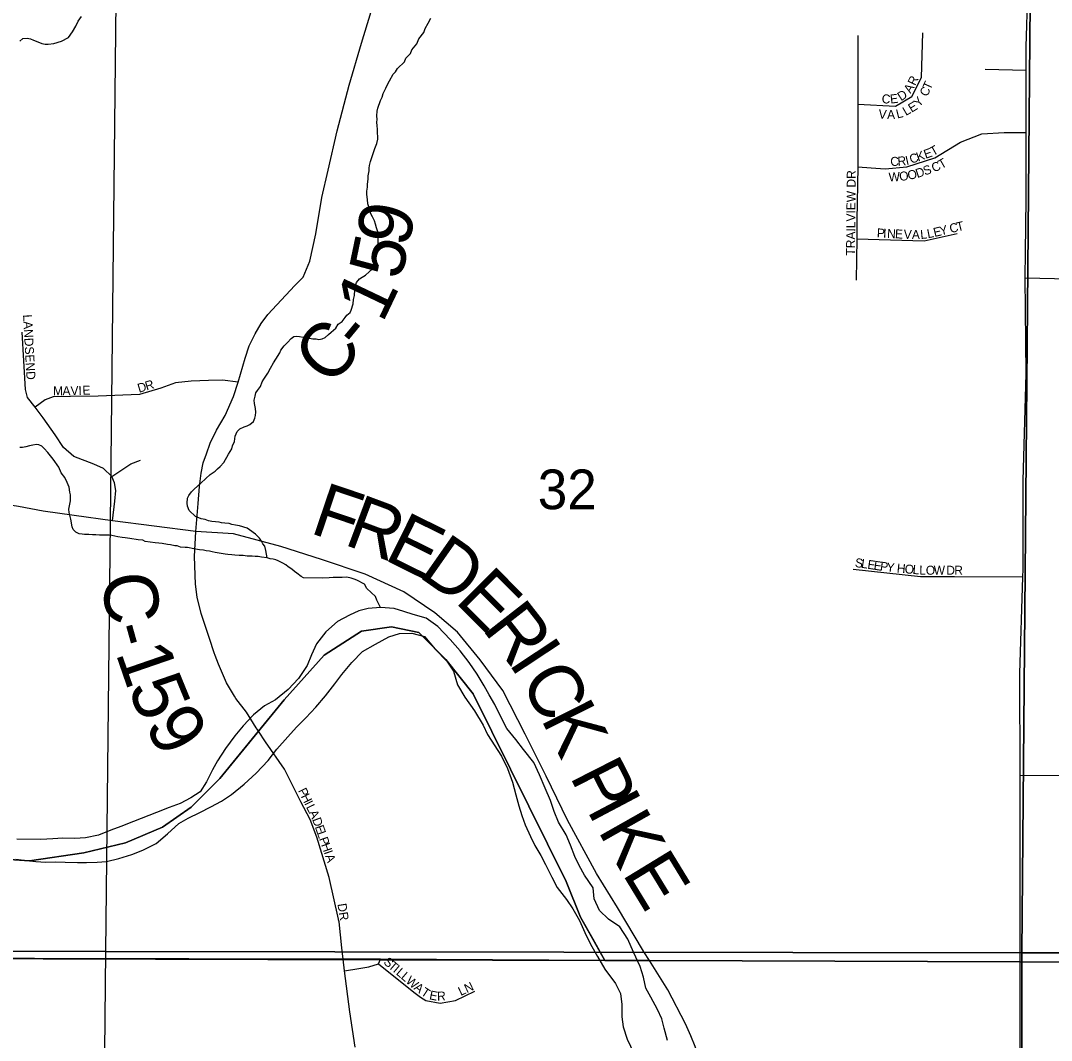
# Model space of a CAD drawing. Extents: x 8.5 to 81.5, y -1.2 to 22.4.
# Drawn here: x 50.14 to 51.227, y 15.672 to 16.747 of the extents above; entities that cross this region are included whole.
import ezdxf

# ---------------------------------------------------------------- set-up
doc = ezdxf.new("R2010")
doc.units = 0
for name, color, linetype in [('GM_X_City_Street', 7, 'Continuous'), ('GM_X_City_Street_Text', 7, 'Continuous'), ('GM_X_Corporation', 7, 'Continuous'), ('GM_X_County_Road', 7, 'Continuous'), ('GM_X_County_Road_Text', 7, 'Continuous'), ('GM_X_Major_River', 7, 'Continuous'), ('GM_X_Minor_River', 7, 'Continuous'), ('GM_X_Section', 7, 'Continuous'), ('GM_X_Section_Text', 7, 'Continuous'), ('GM_X_Township', 7, 'Continuous'), ('GM_X_Township_Road', 7, 'Continuous'), ('GM_X_Township_Subdivision', 7, 'Continuous'), ('GM_X_Township_Subdivision_Text', 7, 'Continuous')]:
    doc.layers.add(name, color=color, linetype=linetype)

msp = doc.modelspace()

# ---------------------------------------------------------------- linework, layer by layer
at = {"layer": 'GM_X_City_Street'}
for points in [[(50.475, 15.7999), (50.4653, 15.8438), (50.4521, 15.8864), (50.4453, 15.9048), (50.4353, 15.9235), (50.4181, 15.9579), (50.398, 15.9867), (50.3907, 15.9981), (50.3893, 16.0003), (50.3883, 16.0018)], [(50.4786, 15.7698), (50.4756, 15.797), (50.4752, 15.799), (50.475, 15.7999)]]:
    msp.add_lwpolyline(points, dxfattribs=at)
at = {"layer": 'GM_X_Corporation'}
msp.add_lwpolyline([(49.4527, 15.7601), (50.7559, 15.7562), (50.7302, 15.802), (50.7151, 15.8397), (50.617, 16.0374), (50.5884, 16.0736), (50.5597, 16.1022), (50.531, 16.1083), (50.4993, 16.1037), (50.4601, 16.0781), (50.4178, 16.0313), (50.3499, 15.9483), (50.3198, 15.9181), (50.2896, 15.897), (50.2504, 15.8804), (50.2066, 15.8698), (50.1492, 15.8615), (50.101, 15.8646)], dxfattribs=at)
at = {"layer": 'GM_X_County_Road'}
for points in [[(50.3246, 16.2088), (50.3272, 16.2382), (50.3286, 16.2563), (50.3302, 16.2701), (50.3324, 16.2812), (50.3357, 16.2905), (50.3397, 16.3017), (50.3465, 16.3155), (50.3554, 16.331), (50.3645, 16.3511), (50.3692, 16.3662), (50.3766, 16.3916), (50.3809, 16.4044), (50.3873, 16.4173), (50.3936, 16.4282), (50.4007, 16.4375), (50.429, 16.468), (50.4379, 16.4769), (50.4449, 16.4939), (50.4512, 16.5227), (50.4576, 16.561), (50.464, 16.5898), (50.4736, 16.6313), (50.4864, 16.6792), (50.4992, 16.7236), (50.5134, 16.7701)], [(50.3246, 16.2088), (50.2366, 16.2198), (50.1963, 16.2257), (50.1637, 16.2302), (50.1377, 16.2351), (50.1106, 16.2391), (50.0822, 16.2433), (50.0473, 16.2529), (50.0206, 16.2634), (49.9985, 16.2787), (49.9767, 16.2983), (49.9534, 16.3306), (49.9379, 16.3518), (49.9304, 16.3621)], [(50.3441, 16.0806), (50.3391, 16.0957), (50.3302, 16.1222), (50.3261, 16.1396), (50.3243, 16.1533), (50.3233, 16.1823), (50.3246, 16.2088)], [(50.8465, 15.6767), (50.841, 15.6895), (50.8222, 15.7253), (50.803, 15.7561), (50.7972, 15.7654), (50.7966, 15.7662), (50.7693, 15.8123), (50.7471, 15.8481), (50.7164, 15.9044), (50.6942, 15.9505), (50.672, 15.9949), (50.6482, 16.0409), (50.6243, 16.0734), (50.6004, 16.1024), (50.5765, 16.1228), (50.5441, 16.145), (50.5031, 16.1638), (50.4571, 16.1791), (50.4144, 16.1928), (50.3642, 16.2061), (50.3246, 16.2088)], [(50.3653, 16.0349), (50.357, 16.0492), (50.3485, 16.0689), (50.345, 16.0779), (50.3441, 16.0806)], [(50.3883, 16.0018), (50.3779, 16.0183), (50.3667, 16.0325), (50.3653, 16.0349)], [(50.4928, 15.6648), (50.4871, 15.7022), (50.4813, 15.7453), (50.4799, 15.7578), (50.4786, 15.7698)], [(50.8935, 15.5017), (50.8905, 15.5051), (50.8802, 15.5222), (50.8752, 15.5348), (50.8734, 15.5393), (50.87, 15.5615), (50.8649, 15.5905), (50.8635, 15.6013), (50.858, 15.6434), (50.8512, 15.6656), (50.8465, 15.6767)]]:
    msp.add_lwpolyline(points, dxfattribs=at)
at = {"layer": 'GM_X_Major_River'}
for points in [[(50.822, 15.672), (50.8185, 15.685), (50.816, 15.6949), (50.8116, 15.7045), (50.8043, 15.7175), (50.7992, 15.7272), (50.7967, 15.7386), (50.7931, 15.7501), (50.7862, 15.765), (50.78, 15.7789), (50.7719, 15.7916), (50.7599, 15.7998), (50.7502, 15.8091), (50.7448, 15.8214), (50.7435, 15.8328), (50.7346, 15.8463), (50.7288, 15.8563), (50.7244, 15.8659), (50.7197, 15.8778), (50.715, 15.8889), (50.7072, 15.902), (50.7025, 15.9134), (50.6986, 15.9249), (50.6931, 15.938), (50.687, 15.9521), (50.6811, 15.9652), (50.67, 15.9787), (50.6619, 15.9895), (50.6526, 16.0011), (50.6464, 16.0134), (50.6398, 16.0264), (50.6339, 16.0364), (50.6288, 16.0461), (50.6214, 16.0584), (50.6129, 16.0707), (50.6033, 16.083), (50.5929, 16.0947), (50.5799, 16.1086), (50.5675, 16.1172), (50.5539, 16.1213), (50.5441, 16.1242), (50.5339, 16.1274), (50.5195, 16.1285), (50.5062, 16.1276), (50.4966, 16.1251), (50.4867, 16.1204), (50.474, 16.1138), (50.4616, 16.103), (50.4519, 16.0903), (50.4467, 16.0786), (50.4419, 16.0673), (50.4329, 16.0538), (50.4221, 16.0419), (50.4086, 16.0312), (50.397, 16.0249), (50.3854, 16.0153), (50.3746, 16.0037), (50.3656, 15.9933), (50.3559, 15.9798), (50.3473, 15.967), (50.3421, 15.9573)], [(50.1348, 15.8631), (50.1461, 15.8617), (50.156, 15.8607), (50.1666, 15.8601), (50.1765, 15.8603), (50.1868, 15.8601), (50.1997, 15.8595), (50.2092, 15.8596), (50.2206, 15.8598), (50.2305, 15.8607), (50.2434, 15.8639), (50.2572, 15.8682), (50.2687, 15.8725), (50.2829, 15.8798), (50.2948, 15.8898), (50.3068, 15.9006), (50.3164, 15.9065), (50.3287, 15.9123), (50.3406, 15.9182), (50.3518, 15.9244), (50.3621, 15.9314), (50.3757, 15.9421), (50.3884, 15.9537), (50.4008, 15.9671), (50.4102, 15.9791), (50.4215, 15.9921), (50.4308, 16.0022), (50.4405, 16.0123), (50.4513, 16.0234), (50.4614, 16.0354), (50.4712, 16.0481), (50.4786, 16.0578), (50.4891, 16.0706), (50.5003, 16.0821), (50.5142, 16.0898), (50.528, 16.0975), (50.5395, 16.1011), (50.5524, 16.1016), (50.5656, 16.0979), (50.5771, 16.0847), (50.5894, 16.0719), (50.5964, 16.0615), (50.6007, 16.047), (50.6084, 16.0339), (50.6184, 16.0197), (50.6276, 16.0043), (50.6323, 15.9947)], [(50.6323, 15.9947), (50.6471, 15.9716), (50.6533, 15.9589), (50.6587, 15.9444), (50.6622, 15.931), (50.6654, 15.9195), (50.6683, 15.9092), (50.6719, 15.8993), (50.6777, 15.887), (50.6821, 15.8774), (50.6883, 15.867), (50.6935, 15.8574), (50.7, 15.844), (50.7055, 15.8332), (50.7155, 15.8205), (50.7222, 15.8108), (50.7291, 15.7985), (50.735, 15.7859), (50.7408, 15.7736), (50.7481, 15.7605), (50.7559, 15.747), (50.7673, 15.732), (50.7725, 15.7216), (50.7737, 15.7098), (50.7739, 15.6969), (50.7752, 15.6862), (50.7795, 15.6732), (50.7864, 15.6586)], [(50.3421, 15.9573), (50.3358, 15.9448), (50.3291, 15.934), (50.3195, 15.9277), (50.308, 15.9219), (50.2965, 15.9175), (50.2831, 15.9125), (50.259, 15.9027), (50.2456, 15.8977), (50.2349, 15.8937), (50.2219, 15.8886), (50.2082, 15.8855), (50.1971, 15.885), (50.1842, 15.8852), (50.1739, 15.8847), (50.161, 15.8838), (50.136, 15.8843)]]:
    msp.add_lwpolyline(points, dxfattribs=at)
at = {"layer": 'GM_X_Minor_River'}
for points in [[(50.1391, 16.7258), (50.1422, 16.7287), (50.1467, 16.729), (50.1501, 16.7282), (50.1535, 16.727), (50.158, 16.725), (50.1622, 16.7234), (50.1656, 16.7226), (50.169, 16.7225), (50.1747, 16.7232), (50.1831, 16.7256), (50.1904, 16.7297), (50.1947, 16.7357), (50.1982, 16.7417), (50.2006, 16.747), (50.2041, 16.7518)], [(50.5137, 16.4929), (50.5146, 16.4967), (50.5154, 16.5009), (50.5155, 16.5047), (50.5164, 16.5096), (50.5168, 16.5134), (50.517, 16.5236), (50.5152, 16.529), (50.5142, 16.5328), (50.5131, 16.5363), (50.5109, 16.5405), (50.5084, 16.5451), (50.5077, 16.5489), (50.5059, 16.5543), (50.5056, 16.5588), (50.505, 16.5642), (50.505, 16.5676), (50.5055, 16.5718), (50.5056, 16.5748), (50.5064, 16.5801), (50.5065, 16.5839), (50.5074, 16.5892), (50.5074, 16.5919), (50.5079, 16.5945), (50.5087, 16.5987), (50.5103, 16.6032), (50.5111, 16.6062), (50.5135, 16.6127), (50.5155, 16.6179), (50.5164, 16.6225), (50.5164, 16.6251), (50.5161, 16.6289), (50.5162, 16.6331), (50.5159, 16.6365), (50.5156, 16.6404), (50.5157, 16.643), (50.5154, 16.6472), (50.5159, 16.6521), (50.5167, 16.6552), (50.5195, 16.6631), (50.5211, 16.6668), (50.5223, 16.6706), (50.5251, 16.6763), (50.5267, 16.68), (50.529, 16.6838), (50.5326, 16.6909), (50.5353, 16.6935), (50.5373, 16.6969), (50.5446, 16.704), (50.5462, 16.7078), (50.5509, 16.7126), (50.5525, 16.7168), (50.5575, 16.7231), (50.5599, 16.7284), (50.565, 16.7348), (50.5666, 16.7393), (50.5697, 16.7446), (50.5725, 16.7502)], [(50.3999, 16.1809), (50.3986, 16.1885), (50.3972, 16.1931), (50.3953, 16.1958), (50.3939, 16.1985), (50.3916, 16.2015), (50.3876, 16.2058), (50.3812, 16.2105), (50.3786, 16.2121), (50.3707, 16.2145), (50.3665, 16.2153), (50.3627, 16.2162), (50.3597, 16.217), (50.3552, 16.2175), (50.3518, 16.2179), (50.3491, 16.2184), (50.3415, 16.2193), (50.3381, 16.2201), (50.3344, 16.2213), (50.3302, 16.2222), (50.3242, 16.2246), (50.3175, 16.2308), (50.3157, 16.2354), (50.3154, 16.2384), (50.3159, 16.2437), (50.3174, 16.2467), (50.3202, 16.2505), (50.3229, 16.2535), (50.3264, 16.2564), (50.3298, 16.2598), (50.3353, 16.2646), (50.3399, 16.2687), (50.3449, 16.2724), (50.3476, 16.2746), (50.3503, 16.2772), (50.3542, 16.2814), (50.3589, 16.2904), (50.3625, 16.296), (50.3633, 16.299), (50.3653, 16.3036), (50.3662, 16.3092), (50.3682, 16.3141), (50.3709, 16.3171), (50.3755, 16.3189), (50.3789, 16.32), (50.3816, 16.3215), (50.3854, 16.3248), (50.387, 16.3282), (50.3875, 16.3309), (50.3879, 16.3347), (50.3876, 16.3385), (50.3866, 16.3438), (50.3863, 16.3472), (50.3871, 16.3514), (50.388, 16.3548), (50.3895, 16.3574), (50.3927, 16.3615), (50.3946, 16.3664), (50.3962, 16.3695), (50.4005, 16.3755), (50.4033, 16.3811), (50.4064, 16.3864), (50.4088, 16.3905), (50.4131, 16.3972), (50.4143, 16.3999), (50.4178, 16.4044), (50.4213, 16.4081), (50.4252, 16.4122), (50.4279, 16.4144), (50.4309, 16.4148), (50.434, 16.4143), (50.4377, 16.4135), (50.4419, 16.413), (50.4445, 16.4126), (50.4479, 16.4118), (50.4514, 16.4117), (50.4544, 16.4112), (50.4578, 16.4119), (50.4609, 16.4134), (50.4644, 16.4164), (50.4674, 16.419), (50.4721, 16.4231), (50.4748, 16.4272), (50.4791, 16.4301), (50.4822, 16.4343), (50.4837, 16.4369), (50.4872, 16.4395), (50.4884, 16.4421), (50.4904, 16.4489), (50.4909, 16.4535), (50.4918, 16.4576), (50.4923, 16.4637), (50.4923, 16.4664), (50.4939, 16.4713), (50.4971, 16.475), (50.5001, 16.4768), (50.5036, 16.4791), (50.5074, 16.4824), (50.5109, 16.4858), (50.5125, 16.4895), (50.5137, 16.4929)], [(50.5195, 16.1285), (50.5155, 16.1364), (50.5141, 16.1402), (50.5051, 16.1487), (50.5026, 16.153), (50.4943, 16.1573), (50.4917, 16.1585), (50.4883, 16.1593), (50.4838, 16.1606), (50.4788, 16.1603), (50.4693, 16.1601), (50.4652, 16.1598), (50.4579, 16.1596), (50.4382, 16.1599), (50.4356, 16.1611), (50.4311, 16.1646), (50.4285, 16.1666), (50.4259, 16.1689), (50.4221, 16.1713), (50.4195, 16.1736), (50.4165, 16.1752), (50.4116, 16.1776), (50.409, 16.1788), (50.406, 16.1796), (50.403, 16.18), (50.3999, 16.1809), (50.3939, 16.1817), (50.3905, 16.1822), (50.3871, 16.1823), (50.384, 16.1827), (50.3787, 16.1828), (50.3746, 16.1833), (50.3704, 16.1833), (50.3659, 16.1838), (50.3624, 16.1839), (50.3583, 16.1843), (50.3556, 16.1848), (50.3492, 16.1857), (50.345, 16.1865), (50.342, 16.1873), (50.339, 16.1878), (50.3356, 16.1882), (50.3326, 16.189), (50.3284, 16.1895), (50.3224, 16.1904), (50.3159, 16.1917), (50.3133, 16.1917), (50.3083, 16.1922), (50.305, 16.1934), (50.3023, 16.1934), (50.2978, 16.1947), (50.2947, 16.1951), (50.2891, 16.196), (50.2857, 16.1964), (50.2819, 16.1969), (50.2713, 16.1982), (50.2687, 16.1994), (50.2637, 16.1999), (50.255, 16.2012), (50.2501, 16.2021), (50.2471, 16.2025), (50.2425, 16.203), (50.2361, 16.2043), (50.2331, 16.2047), (50.2229, 16.2049), (50.2191, 16.205), (50.2156, 16.2051), (50.2119, 16.2055), (50.2073, 16.2056), (50.2047, 16.206), (50.2016, 16.2061), (50.1979, 16.2081), (50.1953, 16.2108), (50.1942, 16.2135), (50.1928, 16.2218), (50.1911, 16.2287), (50.1908, 16.2322), (50.1917, 16.2375), (50.1925, 16.2409), (50.1926, 16.2447), (50.1926, 16.2473), (50.1919, 16.25), (50.1909, 16.2553), (50.1891, 16.2603), (50.1865, 16.2657), (50.1825, 16.2707), (50.1803, 16.2765), (50.174, 16.2849), (50.1685, 16.2919), (50.1648, 16.2961), (50.1622, 16.2985), (50.1592, 16.3001), (50.1565, 16.3005), (50.1527, 16.2998), (50.1493, 16.2991), (50.1455, 16.298), (50.1417, 16.2974), (50.139, 16.2974)]]:
    msp.add_lwpolyline(points, dxfattribs=at)
at = {"layer": 'GM_X_Section'}
for points in [[(49.4527, 15.7683), (50.2298, 15.7659), (50.2406, 16.7675), (49.4527, 16.7724)], [(49.4527, 14.8223), (50.2203, 14.8143), (50.2298, 15.7659), (49.4527, 15.7683)]]:
    msp.add_lwpolyline(points, dxfattribs=at)
for points in [[(50.2406, 16.7675), (51.2044, 16.7664), (51.1955, 15.7645), (50.2298, 15.7659)], [(51.2044, 16.7664), (52.2034, 16.7602), (52.2033, 15.7642), (51.1955, 15.7645)], [(50.2298, 15.7659), (51.1955, 15.7645), (51.1961, 14.7442), (50.219, 14.7462), (50.2203, 14.8143)], [(51.1955, 15.7645), (52.2033, 15.7642), (52.1975, 14.7482), (51.1961, 14.7442)]]:
    msp.add_lwpolyline(points, close=True, dxfattribs=at)
at = {"layer": 'GM_X_Township'}
for points in [[(50.101, 15.8646), (50.1492, 15.8615), (50.2066, 15.8698), (50.2504, 15.8804), (50.2896, 15.897), (50.3198, 15.9181), (50.3499, 15.9483), (50.3907, 15.9981), (50.4178, 16.0313), (50.4601, 16.0781), (50.4993, 16.1037), (50.531, 16.1083), (50.5597, 16.1022), (50.5884, 16.0736), (50.617, 16.0374), (50.7151, 15.8397), (50.7302, 15.802), (50.7431, 15.7791), (50.7559, 15.7562), (50.803, 15.7561), (51.1938, 15.7549), (51.5756, 15.7537)], [(51.5756, 15.7537), (51.1938, 15.7549), (50.803, 15.7561), (50.7559, 15.7562), (50.5195, 15.7577), (50.4799, 15.7578), (49.6657, 15.7594), (49.4527, 15.7601)]]:
    msp.add_lwpolyline(points, dxfattribs=at)
at = {"layer": 'GM_X_Township_Road'}
for points in [[(51.1991, 16.477), (51.1994, 16.5029), (51.2002, 16.5596), (51.2002, 16.6293), (51.2002, 16.6953), (51.2002, 16.7202), (51.2005, 16.7311), (51.2018, 16.7662), (51.2025, 16.7865)], [(51.1938, 15.7681), (51.1938, 15.9514), (51.1937, 16.0591), (51.1967, 16.1609), (51.197, 16.1687), (51.197, 16.2623), (51.2002, 16.3751), (51.1991, 16.4762), (51.1991, 16.477)], [(51.1938, 15.297), (51.1938, 15.3886), (51.1938, 15.7549), (51.1938, 15.7639), (51.1938, 15.7681)]]:
    msp.add_lwpolyline(points, dxfattribs=at)
at = {"layer": 'GM_X_Township_Subdivision'}
for points in [[(51.0228, 16.7317), (51.0228, 16.6595), (51.0227, 16.5934), (51.0218, 16.5369), (51.0215, 16.5172), (51.0208, 16.4737)], [(51.0228, 16.6595), (51.0625, 16.6572), (51.0795, 16.6674), (51.09, 16.6873), (51.0913, 16.7347)], [(51.1571, 16.6963), (51.2002, 16.6953)], [(51.0227, 16.5934), (51.0367, 16.5921), (51.0515, 16.5912), (51.0744, 16.5934), (51.104, 16.6027), (51.1311, 16.6192), (51.1535, 16.6281), (51.1772, 16.6293), (51.2002, 16.6293)], [(51.0215, 16.5172), (51.0926, 16.5151), (51.1273, 16.5231)], [(51.1991, 16.4762), (51.3074, 16.4736), (51.4046, 16.4725)], [(50.2366, 16.2198), (50.2391, 16.2406), (50.2404, 16.252), (50.2389, 16.2601), (50.2362, 16.2666), (50.2271, 16.2751), (50.2169, 16.2797), (50.1961, 16.2876), (50.1851, 16.2971), (50.1764, 16.3107), (50.1635, 16.3287), (50.1551, 16.3397), (50.147, 16.3501), (50.1449, 16.3583), (50.1415, 16.4189)], [(50.3379, 16.3678), (50.3196, 16.3672), (50.3033, 16.3655), (50.2878, 16.3598), (50.2652, 16.353), (50.2215, 16.3515), (50.1923, 16.3509), (50.1741, 16.3507), (50.1658, 16.3475), (50.1551, 16.3397)], [(50.3692, 16.3662), (50.3529, 16.3683), (50.3379, 16.3678)], [(50.2362, 16.2666), (50.2561, 16.2802), (50.2662, 16.2838)], [(51.0177, 16.169), (51.0533, 16.1651), (51.0889, 16.1611), (51.1245, 16.1611), (51.1967, 16.1609)], [(51.1938, 15.9514), (51.282, 15.952), (51.3398, 15.9553), (51.359, 15.9559), (51.3715, 15.9535), (51.3838, 15.9439), (51.4124, 15.9238), (51.563, 15.8167), (51.5714, 15.8083), (51.576, 15.7981), (51.5756, 15.7601)], [(50.4813, 15.7453), (50.4964, 15.7479), (50.5069, 15.7497), (50.5174, 15.7529), (50.5195, 15.7577)], [(50.5174, 15.7529), (50.5546, 15.723), (50.5616, 15.7177), (50.5672, 15.714), (50.5823, 15.7114), (50.5985, 15.7142), (50.6188, 15.7241)]]:
    msp.add_lwpolyline(points, dxfattribs=at)

# ---------------------------------------------------------------- texts
at = {"layer": 'GM_X_City_Street_Text'}
for s, rotation, p in [('P', 296.2596, (50.4321, 15.9354)), ('H', 296.283, (50.4351, 15.9294)), ('I', 296.2524, (50.4387, 15.922)), ('L', 296.2693, (50.4406, 15.9182)), ('A', 295.9981, (50.4435, 15.9123)), ('D', 290.4742, (50.4471, 15.905)), ('E', 289.3506, (50.45, 15.8972)), ('L', 289.3249, (50.4522, 15.8909)), ('P', 289.3472, (50.4544, 15.8847)), ('H', 289.3406, (50.4566, 15.8784)), ('I', 289.3334, (50.4594, 15.8705)), ('A', 289.332, (50.4608, 15.8666)), ('DR', 278.9691, (50.4739, 15.8158))]:
    msp.add_text(s, height=0.00947, rotation=rotation, dxfattribs=at).set_placement(p)
at = {"layer": 'GM_X_County_Road_Text'}
for s, rotation, p in [('9', 77.7777, (50.5483, 16.5071)), ('5', 78.1661, (50.5411, 16.4729)), ('1', 64.5085, (50.5213, 16.4274)), ('C', 48.6066, (50.4662, 16.36)), ('-', 50.4995, (50.4984, 16.3966)), ('F', 341.2751, (50.4436, 16.2075)), ('R', 339.5381, (50.4795, 16.1954)), ('E', 333.6458, (50.5218, 16.1797)), ('D', 325.0014, (50.5579, 16.162)), ('C', 276.2691, (50.2253, 16.163)), ('E', 314.8576, (50.5968, 16.135)), ('R', 307.9643, (50.6256, 16.1062)), ('-', 285.5522, (50.2323, 16.1068)), ('1', 289.0409, (50.2397, 16.0807)), ('I', 303.4866, (50.6536, 16.0704)), ('C', 298.6251, (50.6659, 16.052)), ('5', 292.2904, (50.2524, 16.0443)), ('9', 300.4812, (50.2696, 16.004)), ('K', 296.6172, (50.688, 16.0115)), ('P', 296.9264, (50.7184, 15.9509)), ('I', 297.8669, (50.7362, 15.9158)), ('K', 299.4845, (50.7479, 15.8936)), ('E', 301.416, (50.7736, 15.8483))]:
    msp.add_text(s, height=0.0568, rotation=rotation, dxfattribs=at).set_placement(p)
at = {"layer": 'GM_X_Section_Text'}
msp.add_text('32', height=0.04186, rotation=0, dxfattribs=at).set_placement((50.6852, 16.2322))
at = {"layer": 'GM_X_Township_Subdivision_Text'}
for s, rotation, p in [('R', 64.6251, (51.0833, 16.6782)), ('A', 58.0252, (51.0783, 16.6701)), ('C', 63.3263, (51.0957, 16.6666)), ('T', 65.4841, (51.0992, 16.6736)), ('C', 354.4296, (51.0475, 16.6606)), ('E', 6.6845, (51.0572, 16.6599)), ('D', 33.377, (51.0683, 16.6623)), ('Y', 47.9808, (51.0874, 16.6556)), ('V', 354.6156, (51.0442, 16.6444)), ('A', 1.0403, (51.0536, 16.6436)), ('L', 14.5936, (51.0644, 16.6441)), ('L', 30.0532, (51.0734, 16.6468)), ('E', 31.3071, (51.0794, 16.6502)), ('K', 19.1186, (51.0862, 16.5988)), ('E', 19.7116, (51.0942, 16.6016)), ('T', 29.0733, (51.102, 16.6045)), ('C', 3.0128, (51.0572, 16.594)), ('R', 4.1624, (51.0649, 16.5944)), ('I', 12.9996, (51.074, 16.5951)), ('C', 18.8734, (51.079, 16.5964)), ('C', 22.5389, (51.1027, 16.5873)), ('T', 29.7341, (51.1108, 16.5908)), ('TRAILVIEW DR', 89.4279, (51.0197, 16.4996)), ('W', 2.7919, (51.0554, 16.5777)), ('O', 6.5624, (51.0669, 16.5783)), ('O', 12.0354, (51.0762, 16.5794)), ('D', 18.3134, (51.0854, 16.5814)), ('S', 18.9982, (51.0934, 16.5841)), ('C', 13.5361, (51.1206, 16.5233)), ('T', 13.5361, (51.1279, 16.5251)), ('P', 357.2278, (51.0426, 16.5189)), ('I', 357.2278, (51.0492, 16.5185)), ('N', 357.2278, (51.0534, 16.5183)), ('E', 357.2278, (51.0617, 16.5179)), ('V', 357.2278, (51.0709, 16.5175)), ('A', 359.9459, (51.0797, 16.5171)), ('L', 5.382, (51.089, 16.5171)), ('L', 10.8181, (51.0966, 16.5179)), ('E', 13.5361, (51.1036, 16.5192)), ('Y', 13.5361, (51.1101, 16.5208)), ('LANDSEND', 273.0923, (50.1424, 16.4373)), ('M', 0.0364, (50.174, 16.3523)), ('A', 0.3645, (50.184, 16.3523)), ('V', 1.9314, (50.1926, 16.3524)), ('I', 2.3266, (50.201, 16.3526)), ('E', 2.2961, (50.2052, 16.3528)), ('D', 16.5548, (50.2647, 16.3549)), ('R', 16.9173, (50.2727, 16.3573)), ('S', 351.6922, (51.0192, 16.1714)), ('L', 351.7182, (51.0258, 16.1705)), ('E', 351.6922, (51.0324, 16.1695)), ('E', 351.6938, (51.039, 16.1685)), ('P', 352.0766, (51.0457, 16.1676)), ('Y', 353.9767, (51.0526, 16.1666)), ('H', 354.7331, (51.0635, 16.1655)), ('O', 354.7555, (51.0718, 16.1647)), ('L', 355.0764, (51.0802, 16.164)), ('L', 358.1212, (51.0874, 16.1634)), ('O', 359.9253, (51.0944, 16.1631)), ('W', 359.9988, (51.1027, 16.1631)), ('D', 359.9929, (51.116, 16.1631)), ('R', 359.9941, (51.1244, 16.1631)), ('S', 319.6417, (50.5218, 15.7535)), ('T', 319.6032, (50.5269, 15.7492)), ('I', 319.6425, (50.5319, 15.7449)), ('L', 319.6417, (50.5351, 15.7422)), ('L', 319.6032, (50.5402, 15.7379)), ('W', 319.6269, (50.5453, 15.7335)), ('A', 321.8618, (50.5538, 15.7263)), ('LN', 25.2017, (50.604, 15.7188)), ('T', 327.0206, (50.5612, 15.7206)), ('E', 348.5756, (50.5703, 15.7155)), ('R', 1.2645, (50.5791, 15.714))]:
    msp.add_text(s, height=0.00947, rotation=rotation, dxfattribs=at).set_placement(p)

doc.saveas('drawing.dxf')
